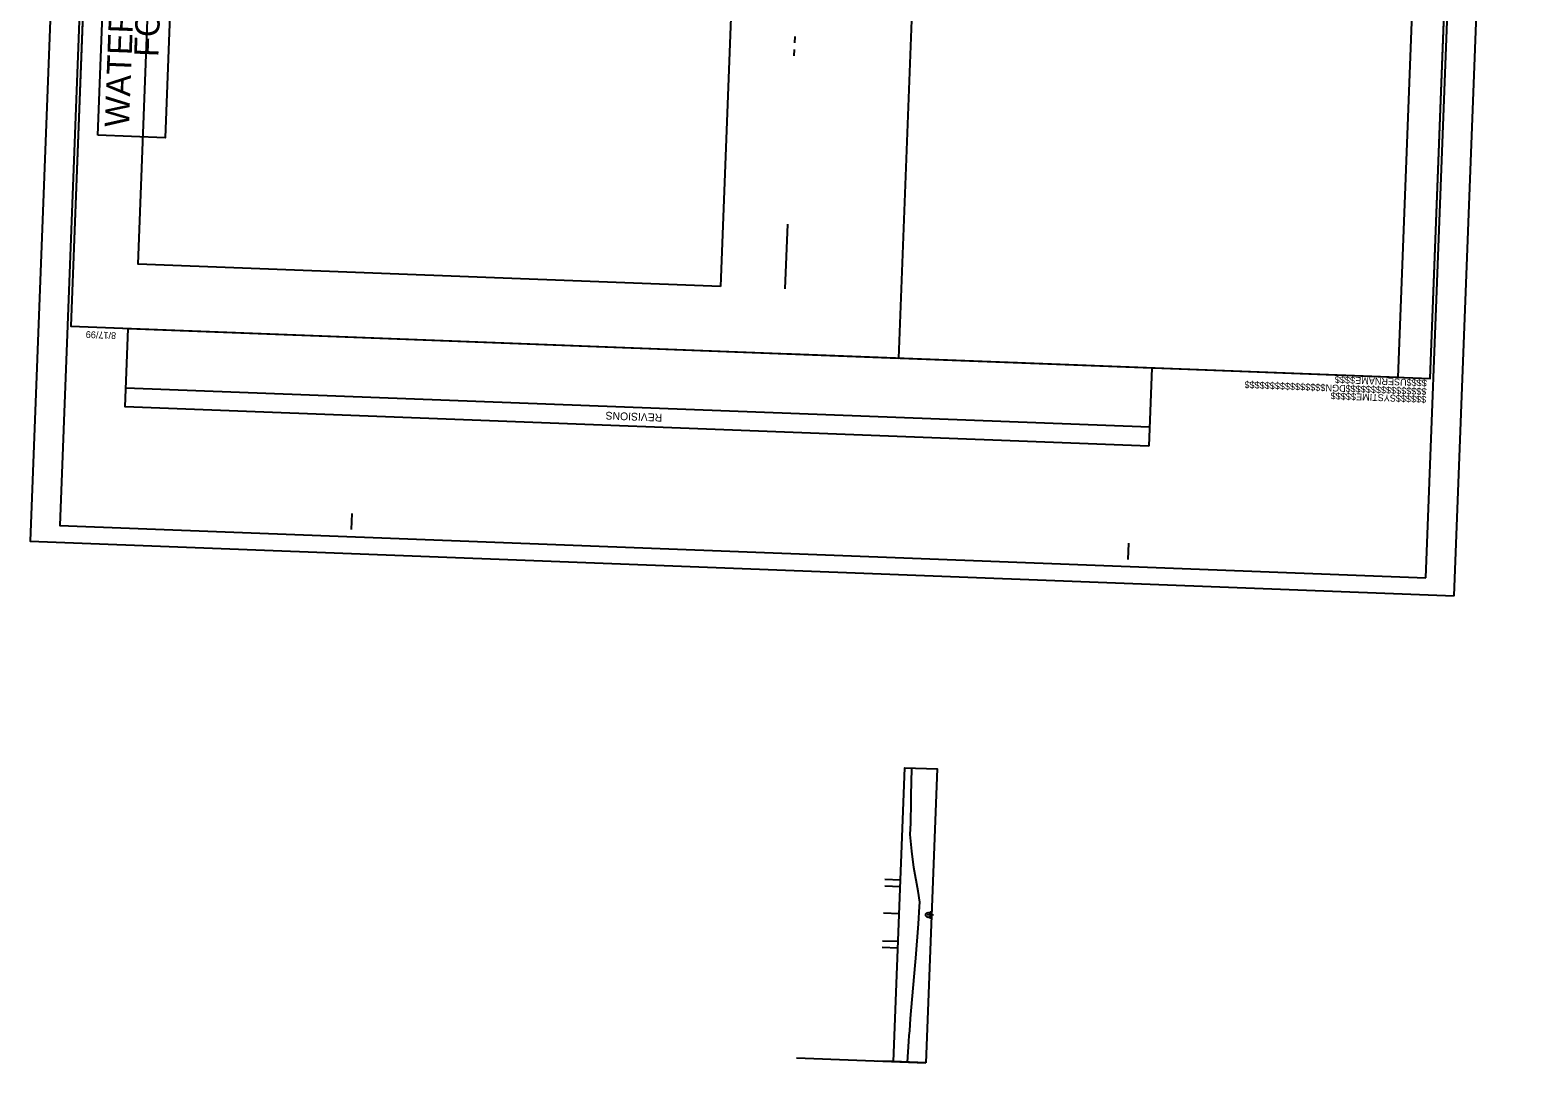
# Model space of a CAD drawing. Extents: x 2097431 to 2097897, y 685861 to 686794.
# Drawn here: x 2097431.2 to 2097896.7, y 685861.1 to 686180.1 of the extents above; entities that cross this region are included whole.
import ezdxf

# ---------------------------------------------------------------- set-up
doc = ezdxf.new("R2010")
doc.units = 0
for name, color, linetype in [('Old_Level_10', 7, 'Continuous'), ('Prop Dimension', 7, 'Continuous'), ('Scratch_Level_3', 7, 'Continuous'), ('Scratch_Level_4', 7, 'Continuous'), ('Scratch_Level_5', 7, 'Continuous'), ('Sheet Block Revision CELL', 7, 'Continuous'), ('Sheet Block System Information CELL', 7, 'Continuous'), ('Sheet Layout Plan Border', 7, 'Continuous'), ('Sheet Plan And Profile CELL', 7, 'Continuous'), ('Sheet Plan CELL', 7, 'Continuous'), ('Sheet Plot Border Inside CELL', 7, 'Continuous'), ('Sheet Plot Border Outside CELL', 7, 'Continuous'), ('Sheet Profile CELL', 7, 'Continuous'), ('Sheet Profile Grid Major CELL', 7, 'Continuous'), ('Sheet Profile Grid Middle CELL', 7, 'Continuous'), ('Sheet Profile Grid Minor CELL', 7, 'Continuous')]:
    doc.layers.add(name, color=color, linetype=linetype)

msp = doc.modelspace()

# ---------------------------------------------------------------- linework, layer by layer
at = {"layer": 'Old_Level_10'}
msp.add_circle((2097708.45, 685906.83), 0.75, dxfattribs=at)
at = {"layer": 'Scratch_Level_3'}
for p, q in [((2097699.83, 685915.54), (2097695.03, 685915.73)), ((2097699.91, 685917.54), (2097695.1, 685917.73)), ((2097699.51, 685907.17), (2097694.71, 685907.35)), ((2097710.07, 685906.76), (2097708.2, 685906.84)), ((2097709.16, 685905.65), (2097709.25, 685907.96)), ((2097699.18, 685898.58), (2097694.38, 685898.76)), ((2097699.1, 685896.58), (2097694.3, 685896.76)), ((2097667.78, 685862.68), (2097707.75, 685861.15)), ((2097697.76, 685861.53), (2097692.96, 685861.72))]:
    msp.add_line(p, q, dxfattribs=at)
at = {"layer": 'Scratch_Level_4'}
msp.add_lwpolyline([(2097452.11, 686147.63), (2097458.35, 686310.29), (2097479.08, 686309.5), (2097472.84, 686146.83)], close=True, dxfattribs=at)
at = {"layer": 'Scratch_Level_5'}
for points in [[(2097443.76, 686088.61), (2097699.44, 686078.8), (2097722.44, 686678.36), (2097503.65, 686686.75), (2097500.59, 686606.79), (2097463.68, 686608.21)], [(2097707.75, 685861.15), (2097697.76, 685861.53), (2097701.24, 685952.31), (2097711.23, 685951.93)]]:
    msp.add_lwpolyline(points, close=True, dxfattribs=at)
msp.add_lwpolyline([(2097702.03, 685861.37), (2097702.45, 685867.73), (2097702.6, 685869.55), (2097702.75, 685871.06), (2097703.05, 685874.85), (2097704.43, 685891.18), (2097704.63, 685893.52), (2097705.48, 685904.06), (2097705.83, 685909.4), (2097705.89, 685910.75), (2097705.35, 685914.15), (2097704.06, 685921.44), (2097703.42, 685926.55), (2097702.91, 685931.65), (2097703.09, 685935.21), (2097703.22, 685941.8), (2097703.23, 685943.86), (2097703.45, 685951.95), (2097703.47, 685952.23)], dxfattribs=at)
at = {"layer": 'Sheet Block Revision CELL'}
msp.add_line((2097776.81, 686057.42), (2097460.78, 686069.54), dxfattribs=at)
msp.add_line((2097776.81, 686057.42), (2097460.78, 686069.54), dxfattribs=at)
msp.add_lwpolyline([(2097776.58, 686051.61), (2097460.56, 686063.73), (2097461.48, 686087.93), (2097777.51, 686075.81)], close=True, dxfattribs=at)
msp.add_lwpolyline([(2097776.58, 686051.61), (2097460.56, 686063.73), (2097461.48, 686087.93), (2097777.51, 686075.81)], close=True, dxfattribs=at)
at = {"layer": 'Sheet Block System Information CELL'}
msp.add_line((2097863.45, 686072.51), (2097863.45, 686072.51), dxfattribs=at)
at = {"layer": 'Sheet Layout Plan Border'}
msp.add_lwpolyline([(2097644.38, 686100.93), (2097464.51, 686107.83), (2097482.9, 686587.46), (2097542.88, 686585.16), (2097545.95, 686665.12), (2097665.84, 686660.52)], close=True, dxfattribs=at)
at = {"layer": 'Sheet Plan And Profile CELL'}
for p, q in [((2097876.45, 686672.46), (2097853.46, 686072.9)), ((2097863.45, 686072.51), (2097863.45, 686072.51)), ((2097863.45, 686072.51), (2097863.45, 686072.51)), ((2097863.45, 686072.51), (2097863.45, 686072.51)), ((2097863.45, 686072.51), (2097863.45, 686072.51)), ((2097863.45, 686072.51), (2097863.45, 686072.51)), ((2097530.41, 686025.84), (2097530.61, 686030.84)), ((2097770.24, 686016.64), (2097770.43, 686021.64))]:
    msp.add_line(p, q, dxfattribs=at)
msp.add_lwpolyline([(2097466.75, 686688.17), (2097443.76, 686088.61), (2097863.45, 686072.51), (2097886.44, 686672.07)], close=True, dxfattribs=at)
at = {"layer": 'Sheet Plot Border Inside CELL'}
msp.add_lwpolyline([(2097862.11, 686010.92), (2097887.65, 686677.03), (2097465.92, 686693.2), (2097440.38, 686027.09)], close=True, dxfattribs=at)
at = {"layer": 'Sheet Plot Border Outside CELL'}
msp.add_lwpolyline([(2097870.88, 686005.38), (2097896.7, 686678.48), (2097457.02, 686695.35), (2097431.2, 686022.24)], close=True, dxfattribs=at)
at = {"layer": 'Sheet Profile CELL'}
for p, q in [((2097863.45, 686072.51), (2097886.44, 686672.07)), ((2097863.45, 686072.51), (2097863.45, 686072.51)), ((2097863.45, 686072.51), (2097863.45, 686072.51)), ((2097863.45, 686072.51), (2097863.45, 686072.51)), ((2097863.45, 686072.51), (2097863.45, 686072.51)), ((2097863.45, 686072.51), (2097863.45, 686072.51)), ((2097863.45, 686072.51), (2097863.45, 686072.51)), ((2097863.45, 686072.51), (2097863.45, 686072.51)), ((2097530.41, 686025.84), (2097530.61, 686030.84)), ((2097770.24, 686016.64), (2097770.43, 686021.64))]:
    msp.add_line(p, q, dxfattribs=at)
msp.add_lwpolyline([(2097466.75, 686688.17), (2097443.76, 686088.61), (2097863.45, 686072.51), (2097886.44, 686672.07)], close=True, dxfattribs=at)
msp.add_lwpolyline([(2097864.02, 686087.5), (2097864.02, 686087.5)], dxfattribs=at)
at = {"layer": 'Sheet Profile Grid Major CELL'}
for p, q in [((2097664.36, 686100.16), (2097665.13, 686120.15)), ((2097853.46, 686072.9), (2097853.46, 686072.9))]:
    msp.add_line(p, q, dxfattribs=at)
msp.add_lwpolyline([(2097663.59, 686080.18), (2097853.46, 686072.9)], dxfattribs=at)
at = {"layer": 'Sheet Profile Grid Middle CELL'}
msp.add_line((2097733.54, 686077.5), (2097753.53, 686076.73), dxfattribs=at)
at = {"layer": 'Sheet Profile Grid Minor CELL'}
for p, q in [((2097667.27, 686176.11), (2097667.35, 686178.11)), ((2097667.12, 686172.11), (2097667.2, 686174.11))]:
    msp.add_line(p, q, dxfattribs=at)

# ---------------------------------------------------------------- texts
at = {"layer": 'Prop Dimension'}
for s, p in [('WATERLINE RELOCATION DETAIL', (2097461.7, 686150.03)), ('FOR PLAN, SEE SHEET 5', (2097470.78, 686171.72))]:
    msp.add_text(s, height=7.5, rotation=87.8037, dxfattribs=at).set_placement(p)
at = {"layer": 'Sheet Block Revision CELL'}
msp.add_text('REVISIONS', height=2.4, rotation=177.8037, dxfattribs=at).set_placement((2097626.39, 686061.57))
msp.add_text('REVISIONS', height=2.4, rotation=177.8037, dxfattribs=at).set_placement((2097626.39, 686061.57))
at = {"layer": 'Sheet Block System Information CELL'}
for s, p in [('$$$$$$$$$$$$$$$$DGN$$$$$$$$$$$$$$$$', (2097862.39, 686069.49)), ('$$$$USERNAME$$$$', (2097862.48, 686072.12)), ('$$$$$$SYSTIME$$$$$', (2097862.29, 686067.07))]:
    msp.add_text(s, height=2.1, rotation=177.8037, dxfattribs=at).set_placement(p)
at = {"layer": 'Sheet Plan And Profile CELL'}
msp.add_text('8/17/99', height=2.1, rotation=177.8037, dxfattribs=at).set_placement((2097457.78, 686086.77))
msp.add_text('8/17/99', height=2.1, rotation=177.8037, dxfattribs=at).set_placement((2097457.78, 686086.77))
at = {"layer": 'Sheet Plan CELL'}
for s, p in [('$$$$$$$$$$$$$$$$DGN$$$$$$$$$$$$$$$$', (2097862.39, 686069.5)), ('$$$$USERNAME$$$$', (2097862.48, 686072.12)), ('$$$$$$SYSTIME$$$$$', (2097862.3, 686067.07))]:
    msp.add_text(s, height=2.1, rotation=177.8037, dxfattribs=at).set_placement(p)

doc.saveas('drawing.dxf')
